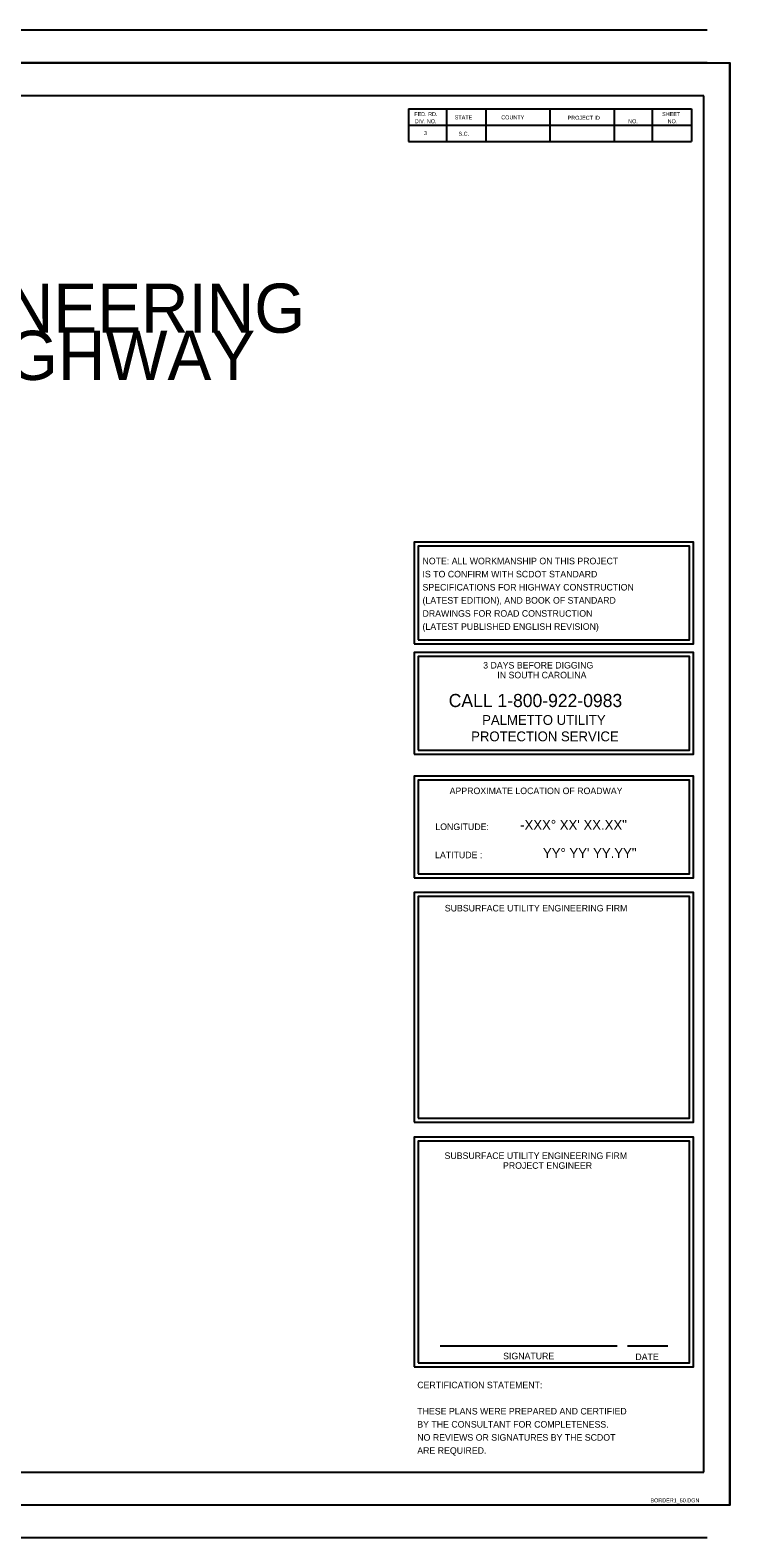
# Model space of a CAD drawing. Extents: x 189971 to 191767, y 195697 to 196847.
# Drawn here: x 191234 to 191767, y 195697 to 196847 of the extents above; entities that cross this region are included whole.
import ezdxf

# ---------------------------------------------------------------- set-up
doc = ezdxf.new("R2010")
doc.units = 0
for name, color, linetype in [('Default', 7, 'Continuous'), ('RD_SHT_Bndy', 7, 'Continuous'), ('RD_SHT_Iplotshp', 7, 'Continuous'), ('RD_SHT_Snap', 7, 'Continuous'), ('RD_SHT_TX', 7, 'Continuous')]:
    doc.layers.add(name, color=color, linetype=linetype)

msp = doc.modelspace()

# ---------------------------------------------------------------- linework, layer by layer
at = {"layer": 'RD_SHT_Bndy'}
for p, q in [((191750, 196847.1), (189990, 196847.1)), ((191750, 196822.1), (189990, 196822.1)), ((191747.6, 196797.1), (190072.6, 196797.1)), ((191747.6, 195747.1), (191747.6, 196797.1)), ((191522.1, 196787.1), (191522.1, 196762.1)), ((191522.1, 196787.1), (191679.1, 196787.1)), ((191551.1, 196787.1), (191551.1, 196762.1)), ((191581.1, 196787.1), (191581.1, 196762.1)), ((191630.1, 196787.1), (191630.1, 196762.1)), ((191679.1, 196787.1), (191679.1, 196762.1)), ((191679.1, 196787.1), (191738.1, 196787.1)), ((191708.1, 196787.1), (191708.1, 196762.1)), ((191738.1, 196787.1), (191738.1, 196762.1)), ((191522.1, 196774.6), (191679.1, 196774.6)), ((191679.1, 196774.6), (191738.1, 196774.6)), ((191522.1, 196762.1), (191679.1, 196762.1)), ((191679.1, 196762.1), (191738.1, 196762.1)), ((190072.6, 195747.1), (191747.6, 195747.1)), ((191750, 195722.1), (189990, 195722.1)), ((191750, 195697.1), (189990, 195697.1))]:
    msp.add_line(p, q, dxfattribs=at)
for points in [[(191526.6, 196379.1), (191739.7, 196379.1), (191739.7, 196456.5), (191526.6, 196456.5)], [(191529.7, 196382.2), (191736.6, 196382.2), (191736.6, 196453.4), (191529.7, 196453.4)], [(191526.6, 196294.9), (191739.7, 196294.9), (191739.7, 196372.4), (191526.6, 196372.4)], [(191529.7, 196298), (191736.6, 196298), (191736.6, 196369.3), (191529.7, 196369.3)], [(191526.6, 196200.6), (191739.7, 196200.6), (191739.7, 196278), (191526.6, 196278)], [(191529.7, 196203.7), (191736.6, 196203.7), (191736.6, 196275), (191529.7, 196275)], [(191526.6, 196014.1), (191739.7, 196014.1), (191739.7, 196189.4), (191526.6, 196189.4)], [(191529.7, 196017.2), (191736.6, 196017.2), (191736.6, 196186.3), (191529.7, 196186.3)], [(191526.6, 195827.6), (191739.7, 195827.6), (191739.7, 196002.8), (191526.6, 196002.8)], [(191529.7, 195830.7), (191736.6, 195830.7), (191736.6, 195999.7), (191529.7, 195999.7)]]:
    msp.add_lwpolyline(points, close=True, dxfattribs=at)
at = {"layer": 'RD_SHT_Iplotshp'}
msp.add_lwpolyline([(189971.4, 196822.1), (191767.4, 196822.1), (191767.4, 195722.1), (189971.4, 195722.1)], close=True, dxfattribs=at)
at = {"layer": 'RD_SHT_Snap'}
msp.add_line((191767.4, 195722.1), (191767.4, 196822.1), dxfattribs=at)
at = {"layer": 'RD_SHT_TX'}
for p, q in [((191546.3, 195843.5), (191681.3, 195843.5)), ((191689.4, 195843.5), (191720, 195843.5))]:
    msp.add_line(p, q, dxfattribs=at)

# ---------------------------------------------------------------- texts
at = {"layer": 'Default'}
for s, p in [('SUBSURFACE UTILITY ENGINEERING', (190535.2, 196616.3)), ('FOR PROPOSED STATE HIGHWAY', (190572.2, 196580.3))]:
    msp.add_text(s, height=37.5, dxfattribs=at).set_placement(p)
at = {"layer": 'RD_SHT_TX'}
for s, height, p in [('FED. RD.', 3, (191526.6, 196781.6)), ('DIV. NO.', 3, (191527, 196776.1)), ('STATE', 3, (191557.5, 196779.1)), ('COUNTY', 3, (191593, 196779.1)), ('PROJECT ID', 3, (191643.6, 196778.8)), ('NO.', 3, (191689.8, 196776.1)), ('SHEET', 3, (191715.7, 196781.6)), ('NO.', 3, (191719.9, 196776.1)), ('3', 3, (191534.1, 196767.1)), ('S.C.', 3, (191560.4, 196766.6)), ('NOTE: ALL WORKMANSHIP ON THIS PROJECT', 5, (191532.9, 196439.7)), ('IS TO CONFIRM WITH SCDOT STANDARD', 5, (191532.9, 196429.7)), ('SPECIFICATIONS FOR HIGHWAY CONSTRUCTION', 5, (191532.9, 196419.7)), ('(LATEST EDITION), AND BOOK OF STANDARD ', 5, (191532.9, 196409.7)), ('DRAWINGS FOR ROAD CONSTRUCTION ', 5, (191532.9, 196399.7)), ('(LATEST PUBLISHED ENGLISH REVISION)', 5, (191532.9, 196389.7)), ('3 DAYS BEFORE DIGGING', 5, (191579.2, 196360.2)), ('IN SOUTH CAROLINA', 5, (191590, 196352.7)), ('CALL 1-800-922-0983', 10, (191552.9, 196330.8)), ('PALMETTO UTILITY', 7.5, (191578.4, 196317.2)), ('PROTECTION SERVICE', 7.5, (191570, 196304.7)), ('APPROXIMATE LOCATION OF ROADWAY', 5, (191553.6, 196264.4)), ('LONGITUDE: ', 5, (191542.7, 196237)), ('-XXX%%d XX\' XX.XX"', 7.5, (191607.4, 196237.2)), ('LATITUDE : ', 5, (191542.5, 196215.5)), ('YY%%d YY\' YY.YY"', 7.5, (191624.8, 196215.7)), ('SUBSURFACE UTILITY ENGINEERING FIRM', 5, (191549.9, 196174.9)), ('SUBSURFACE UTILITY ENGINEERING FIRM', 5, (191549.7, 195986.1)), ('PROJECT ENGINEER', 5, (191594.3, 195978.6)), ('SIGNATURE', 5, (191594.4, 195833.3)), ('DATE', 5, (191695.3, 195832.7)), ('CERTIFICATION STATEMENT:', 5, (191528.9, 195811.2)), ('THESE PLANS WERE PREPARED AND CERTIFIED', 5, (191528.9, 195791.2)), ('BY THE CONSULTANT FOR COMPLETENESS.', 5, (191528.9, 195781.2)), ('NO REVIEWS OR SIGNATURES BY THE SCDOT', 5, (191528.9, 195771.2)), ('ARE REQUIRED.', 5, (191528.9, 195761.2)), ('BORDER1_50.DGN', 3, (191706.8, 195724.2))]:
    msp.add_text(s, height=height, dxfattribs=at).set_placement(p)

doc.saveas('drawing.dxf')
